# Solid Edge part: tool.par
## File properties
Author: Georg
Template: Iso Metric Part.par
Last saved by: Georg
Revision: 5
Application: Solid Edge
Accuracy: 0,990
Face Style: Model Default
Fill Style: Normal
Coef. of Thermal Exp: 0.0
Thermal Conductivity: 0.0
Specific Heat: 0.0
Modulus of Elasticity: 0.0
Poisson's Ratio: 0.0
Yield Stress: 0.0
Ultimate Stress: 0.0
Elongation: 0.0
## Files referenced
!C:\Users\Georg\Desktop\lennuk.asm
..\lennuk.asm
C:\Users\Georg\Desktop\kere.par
C:\Users\Georg\Desktop\tool.par
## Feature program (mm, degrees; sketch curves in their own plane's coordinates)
sketch for "ExtrudedProtrusion_1" plane through (0, 0, -350) normal (0, 0, 1) x-axis (1, 0, 0)
  line (-340, 1927.2062) -> (340, 1927.2028)
extrude "ExtrudedProtrusion_1" add finite 350 along +normal
sketch for "ExtrudedCutout_1" plane through (0, 2252.2023, 0) normal (0, 0, 1) x-axis (1, -5e-06, 0)
  line (-266.9749, -324.9978) -> (266.9782, -324.9978)
extrude "ExtrudedCutout_1" cut finite 175 along -normal
sketch for "ExtrudedProtrusion_2" #1 plane through (0, 2252.2023, 0) normal (0, 0, 1) x-axis (1, -5e-06, 0)
  circle centre (30.0016, 270.0009) radius 12.5
sketch for "ExtrudedProtrusion_2" #2 plane through (0, 2252.2023, 0) normal (0, 0, 1) x-axis (1, -5e-06, 0)
  circle centre (-29.9984, 270.0009) radius 12.5
extrude "ExtrudedProtrusion_2" add finite 40 along +normal
sketch for "ExtrudedProtrusion_3" plane through (30.003, 2522.203, 40) normal (0, 0, 1) x-axis (-1, 0, 0)
  line (-25, -20.0002) -> (85, -20.0002)
  line (85, -20.0002) -> (85, 19.9998)
  line (85, 19.9998) -> (-25, 19.9998)
  line (-25, 19.9998) -> (-25, -20.0002)
extrude "ExtrudedProtrusion_3" add finite 50 along +normal
fillet "Round_1" radius 100
fillet "Round_2" radius 40
fillet "Round_3" radius 14
sketch for "ExtrudedProtrusion_4" plane through (0, 0, -350) normal (0, 0, 1) x-axis (1, 0, 0)
extrude "ExtrudedProtrusion_4" add finite 340 along +normal
chamfer "Chamfer_1" setback 100
sketch for "ExtrudedProtrusion_5" plane through (-0.0001, 1539.8351, -60) normal (0, 0.707107, 0.707107) x-axis (-1, 0, 0)
extrude "ExtrudedProtrusion_5" add finite 0 along +normal
fillet "Round_4" radius 60
swept protrusion "SweptProtrusion_1"
mirror "unnamed Mirror 1" of "SweptProtrusion_1" about plane through (0, 0, 0) normal (-1, 0, 0)
swept protrusion "unnamed SweptProtrusion 1"
sketch for "ExtrudedProtrusion_6" plane through (0, 0, 0) normal (1, 0, 0) x-axis (0, 1, 0)
  circle centre (1584.3876, 1.5135) radius 7.5
extrude "ExtrudedProtrusion_6" add finite 134.3289 symmetric
sketch for "ExtrudedProtrusion_7" plane through (0.0001, 1572.8972, 13.0039) normal (0, 0.707107, 0.707107) x-axis (-1, 0, 0)
  circle centre (0, -16.25) radius 25
extrude "ExtrudedProtrusion_7" add finite 20 symmetric
fillet "Round_5" radius 24
fillet "Round_6" radius 20
fillet "Round_7" radius 11
fillet "Round_8" radius 11
fillet "Round_9" radius 11
fillet "Round_10" radius 60
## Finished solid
Body 1: solid body, 111 faces, 238 edges, 136 vertices, 2 separate solids.
  Faces by surface: blend 30, cylinder 27, plane 23, spline 18, sphere 8, swept 3, torus 2
  Edges by curve: circle 69, intersection 68, line 50, curve on surface 48, spline 2, ellipse 1
Bounding box of the edges (mm; curved faces can reach further): 680.000 x 1299.998 x 440.000, from (-340, 1277.2042, -350) to (340, 2577.202, 90).
Cylindrical faces by radius (mm): R7.5 x2, R12.5 x2, R14 x18, R25 x1, R60 x3, R100 x1
Toroidal faces (ring radius, tube radius in mm): R1 r24 x1, R45 r20 x1
Spherical faces by radius (mm): R14 x8
Planar faces by outward normal: +x 1, +y 2, +z 4, -x 1, -y 2, -z 7, oblique 6
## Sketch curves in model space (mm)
line (0, 1426.6372, -258.7853) -> (0, 1687.6344, -50.8723)
arc centre (0.0001, 1584.3876, 1.5135) radius 75 from (-53.0329, 1546.8876, 39.0135) through (-74.9682, 1585.9301, -0.029) to (-53.0329, 1621.8876, -35.9865)
ellipse centre (-53.0329, 1621.8876, -35.9865) radii 28.1454, 11.1776
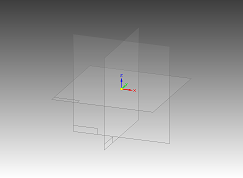
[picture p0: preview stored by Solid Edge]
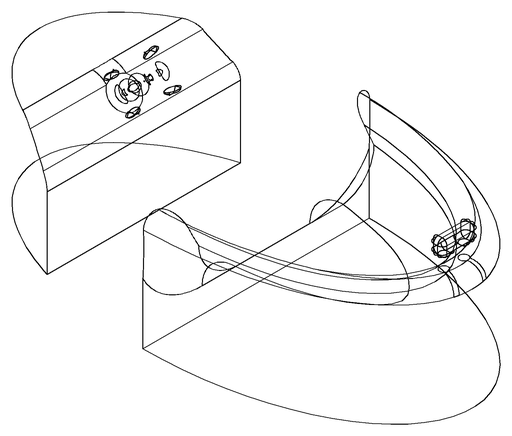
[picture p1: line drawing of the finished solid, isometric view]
